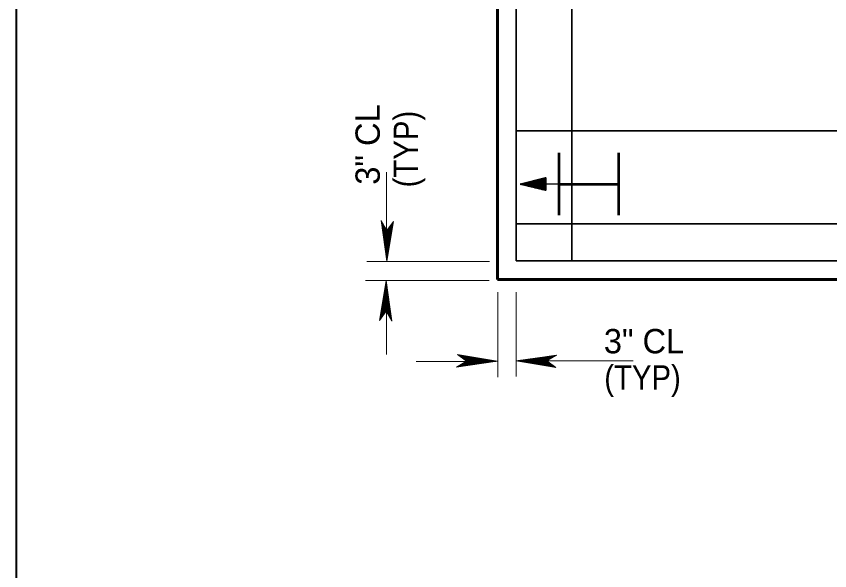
# Model space of a CAD drawing. Extents: x 144 to 252, y 360 to 425.
# Drawn here: x 149.81 to 160.77, y 388.54 to 396 of the extents above; entities that cross this region are included whole.
import ezdxf
from ezdxf.enums import TextEntityAlignment as Align

# ---------------------------------------------------------------- set-up
doc = ezdxf.new("R2010")
doc.units = 0
doc.header["$LTSCALE"] = 0.13
for name, color, linetype, lineweight in [('1', 7, 'Continuous', 40), ('10', 7, 'Continuous', 35), ('16', 7, 'Continuous', 13), ('3', 7, 'Continuous', 13), ('9', 7, 'Continuous', 25)]:
    doc.layers.add(name, color=color, linetype=linetype, lineweight=lineweight)

msp = doc.modelspace()

# ---------------------------------------------------------------- linework, layer by layer
at = {"layer": '1', "lineweight": 60}
for p, q in [((156.2978, 398.2023), (156.2978, 392.4595)), ((156.2978, 395.4595), (156.2978, 395.8819)), ((156.2978, 395.8819), (156.2978, 392.4595)), ((156.2978, 392.4595), (156.2978, 393.9828)), ((180.2978, 392.4595), (156.2978, 392.4595)), ((156.2978, 392.4595), (180.2978, 392.4595))]:
    msp.add_line(p, q, dxfattribs=at)
at = {"layer": '1', "lineweight": 35}
for p, q in [((156.5478, 397.8819), (156.5478, 392.7095)), ((157.2978, 397.8819), (157.2978, 392.7095)), ((156.5478, 395.4595), (156.5478, 395.8819)), ((157.2978, 395.4595), (157.2978, 395.8819)), ((156.5478, 394.4595), (168.3034, 394.4595)), ((156.5478, 393.2095), (168.2861, 393.2095)), ((156.5478, 392.7095), (168.2861, 392.7095))]:
    msp.add_line(p, q, dxfattribs=at)
at = {"layer": '1', "lineweight": 53}
for p, q in [((157.1205, 394.1637), (157.1205, 393.3241)), ((157.9288, 394.1636), (157.9288, 393.324)), ((157.1205, 393.7438), (157.9288, 393.7438))]:
    msp.add_line(p, q, dxfattribs=at)
at = {"layer": '1', "lineweight": 13}
for p, q in [((154.8011, 392.7407), (154.8011, 393.9039)), ((154.8011, 391.4513), (154.8011, 392.2777)), ((156.2742, 391.3564), (155.198, 391.3564)), ((158.1262, 391.3632), (156.559, 391.3632))]:
    msp.add_line(p, q, dxfattribs=at)
at = {"layer": '1', "lineweight": 25}
msp.add_line((157.1205, 393.7438), (156.6205, 393.7438), dxfattribs=at)
at = {"layer": '1'}
msp.add_lwpolyline([(250.3172, 361.9183), (250.3172, 423.9913), (149.8112, 423.9913), (149.8112, 361.9183), (230.3642, 361.9183)], dxfattribs=at)
at = {"layer": '1', "lineweight": 60}
msp.add_lwpolyline([(156.2978, 392.4595), (180.2978, 392.4595), (180.2978, 397.8819)], dxfattribs=at)
at = {"layer": '10'}
for p, q in [((156.9427, 393.7434), (156.6074, 393.7434)), ((156.7587, 393.7285), (156.9427, 393.7208)), ((156.7588, 393.7348), (156.9427, 393.7271)), ((156.9427, 393.7334), (156.759, 393.7411)), ((156.7592, 393.7473), (156.9427, 393.7397)), ((156.9427, 393.6957), (156.7701, 393.7029))]:
    msp.add_line(p, q, dxfattribs=at)
for points in [[(156.9427, 393.8269), (156.9427, 393.66), (156.6074, 393.7433)], [(156.9427, 393.8269), (156.6074, 393.7433), (156.9427, 393.8269)]]:
    msp.add_lwpolyline(points, dxfattribs=at)
msp.add_lwpolyline([(156.6074, 393.7433), (156.9427, 393.8269), (156.9427, 393.66), (156.9427, 393.8269)], close=True, dxfattribs=at)
at = {"layer": '3'}
for p, q in [((154.7273, 393.2529), (154.8051, 392.7042)), ((154.8053, 393.1193), (154.7273, 393.2529)), ((154.7308, 393.2469), (154.8057, 392.7186)), ((154.7328, 393.2434), (154.8057, 392.7294)), ((154.7355, 393.2388), (154.8057, 392.7438)), ((154.7379, 393.2347), (154.8057, 392.7566)), ((154.7379, 393.2347), (154.8057, 392.7566)), ((154.7401, 393.2311), (154.8057, 392.7679)), ((154.7428, 393.2265), (154.8057, 392.7823)), ((154.7452, 393.2224), (154.8057, 392.7951)), ((154.7477, 393.218), (154.8057, 392.8088)), ((154.7502, 393.2136), (154.8057, 392.8227)), ((154.7527, 393.2093), (154.8057, 392.8359)), ((154.7554, 393.2048), (154.8057, 392.8498)), ((154.8051, 392.7042), (154.8943, 393.2418)), ((154.8943, 393.2418), (154.8053, 393.1193)), ((154.8057, 392.7186), (154.892, 393.2386)), ((154.8057, 392.7294), (154.8897, 393.2353)), ((154.8057, 392.7438), (154.8865, 393.2311)), ((154.8057, 392.7566), (154.8838, 393.2273)), ((154.8057, 392.7679), (154.8814, 393.224)), ((154.8057, 392.7823), (154.8783, 393.2197)), ((154.8057, 392.7951), (154.8755, 393.216)), ((154.8057, 392.8088), (154.8726, 393.2119)), ((154.8057, 392.8227), (154.8696, 393.2078)), ((154.8057, 392.8359), (154.8667, 393.2039)), ((154.7577, 393.2008), (154.8057, 392.8624)), ((154.7599, 393.1971), (154.8057, 392.8738)), ((154.7627, 393.1921), (154.8057, 392.8895)), ((154.7654, 393.1877), (154.8057, 392.9033)), ((154.7677, 393.1837), (154.8047, 392.9229)), ((154.7696, 393.1805), (154.8063, 392.9213)), ((154.7722, 393.1761), (154.8063, 392.9352)), ((154.7747, 393.1718), (154.8063, 392.9484)), ((154.7755, 393.1703), (154.8057, 392.9575)), ((154.7777, 393.1664), (154.8057, 392.9695)), ((154.7804, 393.162), (154.8057, 392.9833)), ((154.7832, 393.157), (154.8057, 392.999)), ((154.7857, 393.1529), (154.8057, 393.0116)), ((154.7882, 393.1487), (154.8057, 393.0248)), ((154.7904, 393.1448), (154.8057, 393.0368)), ((154.7931, 393.1402), (154.8057, 393.0513)), ((154.7957, 393.1357), (154.8057, 393.0652)), ((154.798, 393.1317), (154.8057, 393.0778)), ((154.8011, 393.1264), (154.8047, 393.1013)), ((154.8027, 393.1237), (154.8057, 393.1025)), ((154.8051, 393.1196), (154.8051, 392.7042)), ((154.8057, 392.8498), (154.8637, 393.1998)), ((154.8057, 392.8624), (154.8611, 393.1961)), ((154.8057, 392.8738), (154.8586, 393.1927)), ((154.8057, 392.8895), (154.8552, 393.1881)), ((154.8057, 392.9033), (154.8522, 393.184)), ((154.8057, 392.9575), (154.8406, 393.168)), ((154.8057, 392.9695), (154.838, 393.1644)), ((154.8057, 392.9833), (154.835, 393.1603)), ((154.8057, 392.999), (154.8317, 393.1557)), ((154.8057, 393.0116), (154.829, 393.152)), ((154.8057, 393.0248), (154.8262, 393.1481)), ((154.8057, 393.0368), (154.8235, 393.1445)), ((154.8057, 393.0513), (154.8205, 393.1402)), ((154.8057, 393.0652), (154.8175, 393.1361)), ((154.8057, 393.0778), (154.8148, 393.1324)), ((154.8057, 393.0911), (154.8119, 393.1285)), ((154.8057, 393.1025), (154.8095, 393.1251)), ((154.8057, 393.1127), (154.8072, 393.1221)), ((154.8063, 392.9213), (154.8492, 393.1798)), ((154.8063, 392.9352), (154.8462, 393.1756)), ((154.8063, 392.9484), (154.8433, 393.1717)), ((156.188, 392.701), (154.5342, 392.701)), ((156.1834, 392.4479), (154.5171, 392.4479)), ((154.7965, 392.4458), (154.7072, 391.9082)), ((154.7965, 392.0304), (154.7965, 392.4458)), ((154.8742, 391.8971), (154.7965, 392.4458)), ((154.7958, 392.4314), (154.7096, 391.9114)), ((154.7958, 392.4206), (154.7119, 391.9147)), ((154.7958, 392.4062), (154.7151, 391.9189)), ((154.7958, 392.3934), (154.7177, 391.9227)), ((154.7958, 392.3821), (154.7202, 391.926)), ((154.7958, 392.3677), (154.7233, 391.9303)), ((154.7958, 392.3549), (154.7261, 391.934)), ((154.7958, 392.3412), (154.729, 391.9381)), ((154.7958, 392.3273), (154.732, 391.9422)), ((154.8707, 391.9031), (154.7958, 392.4314)), ((154.8688, 391.9066), (154.7958, 392.4206)), ((154.8661, 391.9112), (154.7958, 392.4062)), ((154.8637, 391.9153), (154.7958, 392.3934)), ((154.8637, 391.9153), (154.7958, 392.3934)), ((154.8615, 391.9189), (154.7958, 392.3821)), ((154.8588, 391.9235), (154.7958, 392.3677)), ((154.8564, 391.9276), (154.7958, 392.3549)), ((154.8539, 391.932), (154.7958, 392.3412)), ((154.8513, 391.9364), (154.7958, 392.3273)), ((154.7958, 392.3141), (154.7348, 391.9461)), ((154.7958, 392.3002), (154.7378, 391.9502)), ((154.7958, 392.2876), (154.7405, 391.9539)), ((154.7958, 392.2762), (154.743, 391.9573)), ((154.7958, 392.2605), (154.7463, 391.9619)), ((154.7958, 392.2467), (154.7493, 391.966)), ((154.7953, 392.2287), (154.7524, 391.9702)), ((154.832, 391.9695), (154.7953, 392.2287)), ((154.8488, 391.9407), (154.7958, 392.3141)), ((154.8462, 391.9452), (154.7958, 392.3002)), ((154.8439, 391.9492), (154.7958, 392.2876)), ((154.8417, 391.9529), (154.7958, 392.2762)), ((154.8388, 391.9579), (154.7958, 392.2605)), ((154.8362, 391.9623), (154.7958, 392.2467)), ((154.8339, 391.9663), (154.7969, 392.2271)), ((156.2994, 391.1454), (156.2994, 392.2894)), ((156.5478, 391.1533), (156.5478, 392.2892)), ((154.7953, 392.2147), (154.7554, 391.9744)), ((154.7953, 392.2016), (154.7583, 391.9783)), ((154.7958, 392.1925), (154.761, 391.982)), ((154.7958, 392.1805), (154.7636, 391.9856)), ((154.7958, 392.1667), (154.7666, 391.9897)), ((154.7958, 392.151), (154.7698, 391.9943)), ((154.7958, 392.1384), (154.7726, 391.998)), ((154.7958, 392.1252), (154.7754, 392.0019)), ((154.7958, 392.1132), (154.7781, 392.0055)), ((154.8294, 391.9739), (154.7953, 392.2147)), ((154.8269, 391.9782), (154.7953, 392.2016)), ((154.8261, 391.9797), (154.7958, 392.1925)), ((154.8238, 391.9836), (154.7958, 392.1805)), ((154.8212, 391.988), (154.7958, 392.1667)), ((154.8183, 391.993), (154.7958, 392.151)), ((154.8159, 391.9971), (154.7958, 392.1384)), ((154.8134, 392.0013), (154.7958, 392.1252)), ((154.8112, 392.0052), (154.7958, 392.1132)), ((154.7072, 391.9082), (154.7963, 392.0307)), ((154.7958, 392.0987), (154.7811, 392.0097)), ((154.7958, 392.0848), (154.7841, 392.0139)), ((154.7958, 392.0722), (154.7868, 392.0176)), ((154.7958, 392.0589), (154.7897, 392.0215)), ((154.7958, 392.0475), (154.7921, 392.0249)), ((154.7958, 392.0373), (154.7943, 392.0279)), ((154.8085, 392.0098), (154.7958, 392.0987)), ((154.8059, 392.0143), (154.7958, 392.0848)), ((154.8036, 392.0183), (154.7958, 392.0722)), ((154.7989, 392.0263), (154.7958, 392.0475)), ((154.7963, 392.0307), (154.8742, 391.8971)), ((154.8005, 392.0236), (154.7969, 392.0487)), ((156.2946, 391.3588), (155.7569, 391.4481)), ((155.7569, 391.4481), (155.8794, 391.359)), ((155.8794, 391.359), (155.7458, 391.2811)), ((155.7458, 391.2811), (156.2946, 391.3588)), ((155.7518, 391.2846), (156.2802, 391.3595)), ((155.7553, 391.2866), (156.2693, 391.3595)), ((155.7599, 391.2892), (156.2549, 391.3595)), ((156.2802, 391.3595), (155.7602, 391.4457)), ((156.2693, 391.3595), (155.7634, 391.4434)), ((155.764, 391.2917), (156.2422, 391.3595)), ((155.764, 391.2917), (156.2422, 391.3595)), ((156.2549, 391.3595), (155.7677, 391.4402)), ((155.7677, 391.2938), (156.2308, 391.3595)), ((156.2422, 391.3595), (155.7714, 391.4376)), ((155.7722, 391.2965), (156.2164, 391.3595)), ((156.2308, 391.3595), (155.7747, 391.4352)), ((155.7763, 391.2989), (156.2037, 391.3595)), ((156.2164, 391.3595), (155.779, 391.432)), ((155.7807, 391.3014), (156.1899, 391.3595)), ((156.2037, 391.3595), (155.7827, 391.4292)), ((155.7852, 391.304), (156.1761, 391.3595)), ((156.1899, 391.3595), (155.7868, 391.4263)), ((155.7894, 391.3065), (156.1628, 391.3595)), ((156.1761, 391.3595), (155.7909, 391.4233)), ((155.7939, 391.3092), (156.1489, 391.3595)), ((156.1628, 391.3595), (155.7948, 391.4205)), ((155.7979, 391.3114), (156.1363, 391.3595)), ((156.1489, 391.3595), (155.7989, 391.4175)), ((155.8017, 391.3137), (156.1249, 391.3595)), ((156.1363, 391.3595), (155.8027, 391.4148)), ((156.1249, 391.3595), (155.8061, 391.4123)), ((155.8067, 391.3165), (156.1093, 391.3595)), ((156.1093, 391.3595), (155.8107, 391.409)), ((155.8111, 391.3192), (156.0954, 391.3595)), ((156.0954, 391.3595), (155.8148, 391.406)), ((155.8151, 391.3214), (156.0758, 391.3584)), ((155.8183, 391.3233), (156.0774, 391.36)), ((156.0774, 391.36), (155.819, 391.4029)), ((155.8227, 391.3259), (156.0635, 391.36)), ((156.0635, 391.36), (155.8232, 391.3999)), ((155.8269, 391.3284), (156.0503, 391.36)), ((156.0503, 391.36), (155.827, 391.3971)), ((155.8284, 391.3293), (156.0412, 391.3595)), ((156.0412, 391.3595), (155.8307, 391.3943)), ((155.8323, 391.3315), (156.0292, 391.3595)), ((156.0292, 391.3595), (155.8343, 391.3918)), ((155.8367, 391.3342), (156.0154, 391.3595)), ((156.0154, 391.3595), (155.8384, 391.3887)), ((155.8417, 391.337), (155.9998, 391.3595)), ((155.9998, 391.3595), (155.8431, 391.3855)), ((155.8458, 391.3394), (155.9872, 391.3595)), ((155.9872, 391.3595), (155.8467, 391.3827)), ((155.8501, 391.3419), (155.9739, 391.3595)), ((155.9739, 391.3595), (155.8507, 391.3799)), ((155.8539, 391.3442), (155.9619, 391.3595)), ((155.9619, 391.3595), (155.8543, 391.3773)), ((155.9474, 391.3595), (155.8585, 391.3742)), ((155.8586, 391.3468), (155.9474, 391.3595)), ((155.9336, 391.3595), (155.8627, 391.3712)), ((155.863, 391.3494), (155.9336, 391.3595)), ((155.9209, 391.3595), (155.8663, 391.3685)), ((155.8671, 391.3517), (155.9209, 391.3595)), ((155.9077, 391.3595), (155.8702, 391.3657)), ((155.8723, 391.3548), (155.8974, 391.3584)), ((155.8962, 391.3595), (155.8737, 391.3632)), ((155.875, 391.3564), (155.8962, 391.3595)), ((155.8861, 391.3595), (155.8767, 391.361)), ((155.8792, 391.3588), (156.2946, 391.3588)), ((157.0941, 391.4423), (156.5453, 391.3645)), ((156.5453, 391.3645), (157.083, 391.2752)), ((156.9607, 391.3645), (156.5453, 391.3645)), ((157.0881, 391.4387), (156.5598, 391.3638)), ((156.5598, 391.3638), (157.0797, 391.2776)), ((157.0846, 391.4367), (156.5706, 391.3638)), ((156.5706, 391.3638), (157.0765, 391.2799)), ((157.08, 391.4341), (156.585, 391.3638)), ((156.585, 391.3638), (157.0722, 391.2831)), ((157.0759, 391.4317), (156.5977, 391.3638)), ((157.0759, 391.4317), (156.5977, 391.3638)), ((156.5977, 391.3638), (157.0685, 391.2858)), ((157.0722, 391.4295), (156.6091, 391.3638)), ((156.6091, 391.3638), (157.0652, 391.2882)), ((157.0677, 391.4268), (156.6235, 391.3638)), ((156.6235, 391.3638), (157.0609, 391.2913)), ((157.0636, 391.4244), (156.6362, 391.3638)), ((156.6362, 391.3638), (157.0572, 391.2941)), ((157.0592, 391.4219), (156.65, 391.3638)), ((156.65, 391.3638), (157.0531, 391.297)), ((157.0547, 391.4193), (156.6638, 391.3638)), ((156.6638, 391.3638), (157.049, 391.3)), ((157.0505, 391.4168), (156.6771, 391.3638)), ((156.6771, 391.3638), (157.0451, 391.3028)), ((157.046, 391.4142), (156.691, 391.3638)), ((156.691, 391.3638), (157.041, 391.3058)), ((157.042, 391.4119), (156.7036, 391.3638)), ((156.7036, 391.3638), (157.0373, 391.3085)), ((157.0383, 391.4097), (156.715, 391.3638)), ((156.715, 391.3638), (157.0338, 391.311)), ((157.0332, 391.4068), (156.7307, 391.3638)), ((156.7307, 391.3638), (157.0292, 391.3143)), ((157.0288, 391.4042), (156.7445, 391.3638)), ((156.7445, 391.3638), (157.0252, 391.3173)), ((157.0217, 391.4), (156.7625, 391.3633)), ((156.7625, 391.3633), (157.0209, 391.3204)), ((157.0248, 391.4019), (156.7641, 391.3649)), ((157.0172, 391.3974), (156.7764, 391.3633)), ((156.7764, 391.3633), (157.0168, 391.3234)), ((157.013, 391.3949), (156.7896, 391.3633)), ((156.7896, 391.3633), (157.0129, 391.3262)), ((157.0115, 391.3941), (156.7987, 391.3638)), ((156.7987, 391.3638), (157.0092, 391.329)), ((157.0076, 391.3918), (156.8107, 391.3638)), ((156.8107, 391.3638), (157.0056, 391.3316)), ((157.0032, 391.3892), (156.8245, 391.3638)), ((156.8245, 391.3638), (157.0015, 391.3346)), ((156.9982, 391.3863), (156.8402, 391.3638)), ((156.8402, 391.3638), (156.9968, 391.3378)), ((156.9941, 391.3839), (156.8527, 391.3638)), ((156.8527, 391.3638), (156.9932, 391.3406)), ((156.9898, 391.3814), (156.866, 391.3638)), ((156.866, 391.3638), (156.9892, 391.3434)), ((156.986, 391.3792), (156.878, 391.3638)), ((156.878, 391.3638), (156.9857, 391.3461)), ((156.9813, 391.3765), (156.8925, 391.3638)), ((156.8925, 391.3638), (156.9814, 391.3491)), ((156.9769, 391.3739), (156.9063, 391.3638)), ((156.9063, 391.3638), (156.9772, 391.3521)), ((156.9728, 391.3716), (156.919, 391.3638)), ((156.919, 391.3638), (156.9736, 391.3548)), ((156.9322, 391.3638), (156.9697, 391.3577)), ((156.9676, 391.3685), (156.9425, 391.3649)), ((156.9649, 391.3669), (156.9437, 391.3638)), ((156.9437, 391.3638), (156.9663, 391.3601)), ((156.9538, 391.3638), (156.9632, 391.3623)), ((156.9605, 391.3643), (157.0941, 391.4423)), ((157.083, 391.2752), (156.9605, 391.3643))]:
    msp.add_line(p, q, dxfattribs=at)
at = {"layer": '9'}
for p, q in [((156.6431, 393.7523), (156.7592, 393.7473)), ((156.6647, 393.7576), (156.7593, 393.7537)), ((156.6863, 393.763), (156.7595, 393.7599)), ((156.7078, 393.7683), (156.7597, 393.7663)), ((156.7294, 393.7738), (156.7598, 393.7725)), ((156.7511, 393.7791), (156.76, 393.7788)), ((156.7593, 393.7537), (156.9427, 393.746)), ((156.7595, 393.7599), (156.9427, 393.7523)), ((156.7597, 393.7663), (156.9427, 393.7585)), ((156.7598, 393.7725), (156.9427, 393.7648)), ((156.76, 393.7788), (156.9427, 393.7712)), ((156.7727, 393.7845), (156.9427, 393.7774)), ((156.7943, 393.7899), (156.9427, 393.7837)), ((156.8158, 393.7953), (156.9427, 393.79)), ((156.8374, 393.8007), (156.9427, 393.7963)), ((156.859, 393.8061), (156.9427, 393.8026)), ((156.8806, 393.8114), (156.9427, 393.8088)), ((156.9022, 393.8168), (156.9427, 393.8152)), ((156.9238, 393.8222), (156.9427, 393.8214)), ((156.6181, 393.7407), (156.7588, 393.7348)), ((156.6214, 393.7468), (156.759, 393.7411)), ((156.6485, 393.7332), (156.7587, 393.7285)), ((156.6789, 393.7256), (156.7586, 393.7222)), ((156.7092, 393.718), (156.7584, 393.716)), ((156.7397, 393.7104), (156.7583, 393.7097)), ((156.7583, 393.7097), (156.9427, 393.7019)), ((156.7584, 393.716), (156.9427, 393.7082)), ((156.7586, 393.7222), (156.9427, 393.7146)), ((156.8004, 393.6953), (156.9427, 393.6893)), ((156.8308, 393.6877), (156.9427, 393.6831)), ((156.8612, 393.6803), (156.9427, 393.6768)), ((156.8917, 393.6727), (156.9427, 393.6705)), ((156.922, 393.6651), (156.9427, 393.6642))]:
    msp.add_line(p, q, dxfattribs=at)
at = {"layer": '9', "lineweight": 40}
msp.add_lwpolyline([(156.6074, 393.7433), (156.9427, 393.8269), (156.9427, 393.66)], close=True, dxfattribs=at)

# ---------------------------------------------------------------- texts
at = {"layer": '16'}
msp.add_text('3" CL', height=0.3281, rotation=90, dxfattribs=at).set_placement((154.7102, 394.8176), align=Align.RIGHT)
at = {"layer": '16', "width": 0.9}
msp.add_text('(TYP)', height=0.3281, rotation=90, dxfattribs=at).set_placement((155.2261, 394.7303), align=Align.RIGHT)
at = {"layer": '16'}
msp.add_text('3" CL', height=0.3281, dxfattribs=at).set_placement((157.7294, 391.465))
at = {"layer": '16', "width": 0.9}
msp.add_text('(TYP)', height=0.3281, dxfattribs=at).set_placement((157.735, 390.9763))

doc.saveas('drawing.dxf')
